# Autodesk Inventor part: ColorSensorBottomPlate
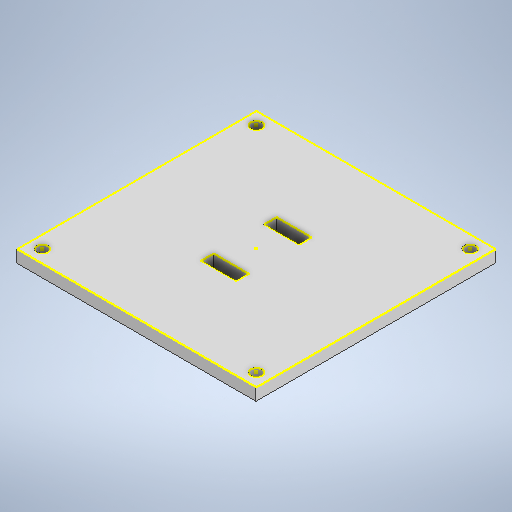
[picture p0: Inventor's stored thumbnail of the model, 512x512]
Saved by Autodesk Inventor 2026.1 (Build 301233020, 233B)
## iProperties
Created: 2026-11
Part Number: ColorSensorBottomPlate
Material: Generic
Document SubType Name: Modeling
Designer: hp
Density: 1 g/cm^3
Appearance: Default
Author: hp
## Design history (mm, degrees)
sketch "Sketch1"
  geometry: L1 (-32.5, 32.5)-(32.5, 32.5); L2 (32.5, 32.5)-(32.5, -32.5); L3 (32.5, -32.5)-(-32.5, -32.5); L4 (-32.5, -32.5)-(-32.5, 32.5); L5 (-32.5, 32.5)-(32.5, -32.5); L6 (32.5, 32.5)-(-32.5, -32.5); L7 (47.5, -47.5)-(47.5, 47.5); L8 (47.5, 47.5)-(-47.5, 47.5); L9 (-47.5, 47.5)-(-47.5, -47.5); L10 (-47.5, -47.5)-(47.5, -47.5); L11 (17, -17)-(17, 17); L12 (17, 17)-(-17, 17); L13 (-17, 17)-(-17, -17); L14 (-17, -17)-(17, -17); L15 (7, 15)-(-7, 15); L16 (-7, 15)-(-7, 10); L17 (-7, 10)-(7, 10); L18 (7, 10)-(7, 15); L19 (7, -10)-(-7, -10); L20 (-7, -10)-(-7, -15); L21 (-7, -15)-(7, -15); L22 (7, -15)-(7, -10); 5 further points
  constraints: 44 end point, 10 parallel, 6 midpoint, 5 perpendicular, 3 horizontal, 2 vertical alignment, 6 other
  dimensions: "d0" = 65 distance of L2.end L3.end; "d1" = 65 distance of L1.end L2.end; "d2" = 15 distance between parallel lines of L2 L7; "d5" = 34 distance of L11.start L11.end; "d6" = 14 distance of L17.end L16.end; "d7" = 5 distance of L16.end L15.end; "d8" = 14 distance of L21.end L20.end; "d9" = 5 distance of L20.end L19.end; "d10" = 2 distance between parallel lines of L12 L15; "d11" = 2 distance between parallel lines of L14 L21
extrude "Extrusion1" new body sketch "Sketch1" distance "d3" = 5; taper "d4" = 0 deg
sketch "Sketch2"
  geometry: L1 (-47.5, -47.5)-(47.5, -47.5) reference; L2 (47.5, -47.5)-(47.5, 47.5) reference; L3 (47.5, 47.5)-(-47.5, 47.5) reference; L4 (-47.5, 47.5)-(-47.5, -47.5) reference; L5 (-7, 10)-(-7, 15) reference; L6 (-7, 15)-(7, 15) reference; L7 (7, 15)-(7, 10) reference; L8 (7, 10)-(-7, 10) reference; L9 (-7, -15)-(-7, -10) reference; L10 (-7, -10)-(7, -10) reference; L11 (7, -10)-(7, -15) reference; L12 (7, -15)-(-7, -15) reference; L13 (0, 47.5)-(0, -47.5); L14 (-47.5, 0)-(47.5, 0); L15 (0, -47.5)-(0, 47.5); C1 r 2.25 at (-42.5, 42.5); C2 r 2.25 at (42.5, 42.5); C3 r 2.25 at (-42.5, -42.5); C4 r 2.25 at (42.5, -42.5); 1 further point
  constraints: 6 end point, 5 symmetric about line, 4 centre point, 4 midpoint, 3 other
  dimensions: "d12" = 4.5 diameter of C1; "d13" = 5 distance from line of L4 C1.centre; "d14" = 5 distance from line of L3 C1.centre
extrude "Extrusion2" cut sketch "Sketch2" extent not by distance; stored distance "d15" = 0; taper "d16" = 0 deg
sketch "Sketch3"
  geometry: L1 (-47.5, -47.5)-(47.5, -47.5) reference; L2 (47.5, -47.5)-(47.5, 47.5) reference; L3 (47.5, 47.5)-(-47.5, 47.5) reference; L4 (-47.5, 47.5)-(-47.5, -47.5) reference; L5 (-7, 10)-(-7, 15) reference; L6 (-7, 15)-(7, 15) reference; L7 (7, 15)-(7, 10) reference; L8 (7, 10)-(-7, 10) reference; L9 (-7, -15)-(-7, -10) reference; L10 (-7, -10)-(7, -10) reference; L11 (7, -10)-(7, -15) reference; L12 (7, -15)-(-7, -15) reference; C1 r 2.25 at (42.5, 42.5) reference; C2 r 2.25 at (-42.5, -42.5) reference; C3 r 2.25 at (-42.5, 42.5) reference; C4 r 2.25 at (42.5, -42.5) reference; 1 further point
  node "Projected Loop2"
body "Solid1"
node "Projected Loop1"
